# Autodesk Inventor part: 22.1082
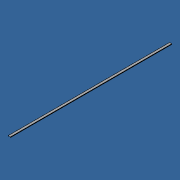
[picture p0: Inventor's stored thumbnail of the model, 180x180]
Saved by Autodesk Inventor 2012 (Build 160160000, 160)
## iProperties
Created: 2007-05
Part Number: 22.1082
Material: PVC-U
Document SubType Name: Modeling
Designer: Andy Moles
Density: 1.4 g/cm^3
Description: CONDUIT 32 TOP
Stock Number: 22.1082 CONDUIT 32 TOP
Author: Andy Moles
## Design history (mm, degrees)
sketch "Sketch1"
  geometry: L1 (-13.3, 0)-(0, 0); L2 (-15, -6.5)-(-15, -1.7); L3 (-13.8, -1.7)-(-13.8, -4.51); L4 (0, -1.2)-(-13.3, -1.2); L5 (0, 0)-(0, 38.062); L6 (13.3, 0)-(0, 0); L7 (15, -6.5)-(15, -1.7); L8 (13.8, -1.7)-(13.8, -4.51); L9 (0, -1.2)-(13.3, -1.2); A1 r 1.7 centre (-13.3, -1.7) between (-13.3, 0) and (-15, -1.7); A2 r 1.5 centre (-13.5, -6.5) between (-15, -6.5) and (-13.35, -5.008); A3 r 0.5 centre (-13.3, -4.51) between (-13.8, -4.51) and (-13.35, -5.008); A4 r 0.5 centre (-13.3, -1.7) between (-13.3, -1.2) and (-13.8, -1.7); A5 r 1.7 centre (13.3, -1.7) between (15, -1.7) and (13.3, 0); A6 r 1.5 centre (13.5, -6.5) between (13.35, -5.008) and (15, -6.5); A7 r 0.5 centre (13.3, -4.51) between (13.35, -5.008) and (13.8, -4.51); A8 r 0.5 centre (13.3, -1.7) between (13.8, -1.7) and (13.3, -1.2)
  constraints: 18 end point, 16 point on circle, 11 symmetric about line, 8 centre point, 4 other
extrude "Extrusion2" new body sketch "Sketch1" stored distance "d3" = 2000; taper "d4" = 0 deg
body "Solid2"
